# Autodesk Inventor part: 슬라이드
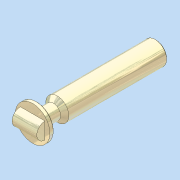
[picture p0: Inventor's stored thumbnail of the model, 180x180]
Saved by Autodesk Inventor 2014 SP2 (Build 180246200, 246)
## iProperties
Company: 한국ATC센터
Created: 2014-10
Part Number: 슬라이드
Document SubType Name: Modeling
Designer: 한국ATC센터
Density: 7.86 g/cm^3
Material: 강, 연강
Mass: 728.405 g
Surface Area: 164.68 cm^2
Volume: 92.6724 cm^3
Appearance: 티타늄 - 광택
Author: KYOUNG IL JANG
Revision Number: 1
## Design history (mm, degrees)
sketch "스케치1"
  geometry: L1 (-14, 195)-(-14, 171) reference; L2 (19, 106.5)-(-19, 106.5) reference; L3 (0, 106.5)-(0, 256.5); L4 (0, 256.5)-(-14, 256.5); L5 (-14, 256.5)-(-14, 136.5); L6 (-14, 111.5)-(-21, 111.5); L7 (-21, 111.5)-(-21, 106.5); L8 (-21, 106.5)-(0, 106.5); L9 (-14, 111.5)-(-9, 111.5); L10 (-9, 111.5)-(-9, 131.5); L11 (-9, 131.5)-(-14, 136.5); L12 (-14, 136.5)-(-14, 111.5); 1 further point
  constraints: 24 end point, 5 perpendicular, 3 parallel, 1 collinear, 1 horizontal, 1 midpoint, 1 point on line, 1 vertical, 4 other
  dimensions: "d0" = 5 distance between parallel lines of L6 L8; "d1" = 42 diameter of L7 L3; "d2" = 150 distance of L3.start L3.end; "d3" = 135 deg angle of L11 L5; "d4" = 18 diameter of L10 L3; "d5" = 30 distance from line of L5.end L8
revolve "회전1" sketch "스케치1" stored, may be unused: angle "d6" = 90 deg
chamfer "모따기1" distance "d7" = 1; stored, may be unused: second distance "d8" = 2, angle "d9" = 45 deg
fillet "모깎기1" dims "d10" = 2
sketch "스케치2"
  geometry: L1 (21, 106.5)-(-21, 106.5) reference; L2 (-15, 96.5)-(15, 96.5); L3 (15, 96.5)-(15, 106.5); L4 (15, 106.5)-(-15, 106.5); L5 (-15, 106.5)-(-15, 96.5); 2 further points
  constraints: 8 end point, 2 midpoint, 2 parallel, 1 horizontal, 1 perpendicular, 1 point on line
  dimensions: "d11" = 20 diameter of L2 L4; "d12" = 30 distance between parallel lines of L3 L5
revolve "회전2" sketch "스케치2" stored, may be unused: angle "d13" = 180 deg
node "솔리드1"
